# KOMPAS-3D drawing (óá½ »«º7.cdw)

Referenced files: вал-0204.cdw
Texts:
  Вал
  Noncommercial version
  1. Термообработка, нормализация НВ 140... 187.
  2. Неуказанные предельные отклонения размеров:
  отверстий по Н14, валов по h14.
  3. Кромки притупить R   0,3.
  Symbol type A
  Ra1.25
  Ra0.63
  Ra3.2
  Сталь 45  ГОСТ 1050-88
  ДГТУ
Dimensions and other numbers on the sheet: 272; 17; 77; 187; 110; 60; 56; 50; 2; 45; 0,03; 0.005; 0,05; 0,008; 0,04; 5; 26; 8; 0.025; 14; 39,5; 5,5; 30; 40; 90; 1; 35; 1:1; 5.68; 0; 3; 4; 6; 7; 9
